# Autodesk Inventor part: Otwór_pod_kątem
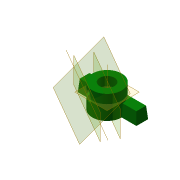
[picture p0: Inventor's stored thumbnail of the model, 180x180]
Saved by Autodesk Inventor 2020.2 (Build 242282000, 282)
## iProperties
Created: 2005-08
Part Number: Otwór_pod_kątem
Document SubType Name: Modeling
Designer: F.Stasiak
Manufacturer: Standard
Standards Organization: Custom
Density: 1 g/cm^3
Material: Ogólny
Appearance: Ciemnozielona
Manager: www.cadconsulting.pl
Company: Fabian Stasiak CAD Consulting
Author: F.Stasiak
Subject: Zbiór ćwiczeń. Autodesk Inventor 2020. Kurs podstawowy
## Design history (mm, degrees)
sketch "Szkic1"
  geometry: L1 (0, 0)-(100, 0); L2 (100, 0)-(100, 20); L3 (100, 20)-(0, 20); L4 (0, 20)-(0, 0); L5 (0, 10)-(100, 10); C1 r 25 at (50, 0)
  constraints: 10 end point, 3 midpoint, 2 parallel, 1 centre point, 1 horizontal, 1 perpendicular
  dimensions: "d0" = 100 distance of L1.start L1.end; "d1" = 20 distance of L3.end L1.start; "d2" = 50 diameter of C1
extrude "Wyciągnięcie proste1" new body sketch "Szkic1" distance "d3" = 20; taper "d4" = -5 deg
extrude "Wyciągnięcie proste2" join sketch "Szkic1" distance "d5" = 40; taper "d6" = 0 deg
sketch "Szkic2"
  geometry: C1 r 25 at (0, 0) reference; C2 r 12.5 at (0, 0)
  constraints: 1 centre point
  dimensions: "d7" = 25 diameter of C2
extrude "Wyciągnięcie proste3" cut sketch "Szkic2" distance "d8" = 40; taper "d9" = 0 deg
node "Oś konstrukcyjna1"
node "Płaszczyzna obrotu"
node "Płaszczyzna konstrukcyjna2"
node "Płaszczyzna konstrukcyjna3"
node "Oś konstrukcyjna2"
node "Płaszczyzna pochylenia"
sketch "Szkic3"
  geometry: L1 (0, -42.413)-(0, 89.549) reference; L2 (-49.282, 0)-(36.962, 0) reference; 1 further point
  constraints: 2 point on line
hole "Otwór1" sketch "Szkic3" at (0, 0) diameter "d13" = 10; stored, may be unused: countersink angle "d17" = 90 deg, drill point angle "d19" = 118 deg; dims "d14" = 6, "d15" = 20, "d16" = 5, "d18" = 20
node "Bryła1"
node "Korpusy bryłowe"
node "Korpusy powierzchniowe"
other parameters: "d10" = -30 deg, "d11" = -15, "d12" = 45 deg
